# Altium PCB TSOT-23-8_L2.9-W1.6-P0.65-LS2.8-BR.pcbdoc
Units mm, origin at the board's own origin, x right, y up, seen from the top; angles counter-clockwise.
Board outline 16.47 x 15.99 mm, 2 copper layers (Top Layer, Bottom Layer), stack 0 mm thick; 1 components, 0 nets, 8 pads, 0 vias.
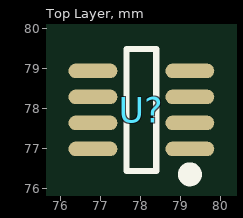
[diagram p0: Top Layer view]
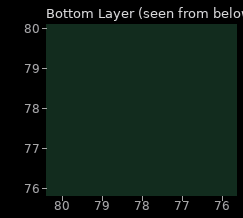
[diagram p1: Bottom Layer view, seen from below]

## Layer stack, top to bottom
Top Layer: signal copper (thickness not stored)
Bottom Layer: signal copper (thickness not stored)

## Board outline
86.322,69.85 69.85,69.85 69.85,85.836 86.322,85.836

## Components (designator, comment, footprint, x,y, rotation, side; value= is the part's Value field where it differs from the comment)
U? "" TSOT-23-8_L2.9-W1.6-P0.65-LS2.8-BR 78.022,77.959 r0 top

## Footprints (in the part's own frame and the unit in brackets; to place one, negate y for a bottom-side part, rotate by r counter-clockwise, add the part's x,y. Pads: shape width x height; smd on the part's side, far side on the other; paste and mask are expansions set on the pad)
TSOT-23-8_L2.9-W1.6-P0.65-LS2.8-BR [mm]
  oval 1.222x0.364 smd: 1(1.211,-0.975) 2(1.211,-0.325) 3(1.211,0.325) 4(1.211,0.975) 5(-1.211,0.975) 6(-1.211,0.325) 7(-1.211,-0.325) 8(-1.211,-0.975)
  silkscreen extent -0.37,-1.76 1.36,1.53

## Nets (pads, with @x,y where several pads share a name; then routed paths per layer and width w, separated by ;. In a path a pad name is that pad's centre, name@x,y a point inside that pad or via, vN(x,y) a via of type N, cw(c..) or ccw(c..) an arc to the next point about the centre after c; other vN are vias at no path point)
pads on no net: U?.1 U?.2 U?.3 U?.4 U?.5 U?.6 U?.7 U?.8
